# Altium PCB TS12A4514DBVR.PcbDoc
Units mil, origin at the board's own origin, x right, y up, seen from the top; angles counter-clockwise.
Board outline 588 x 300 mil, 2 copper layers (Top, Bottom), stack 61.811 mil thick; 3 components, 5 nets, 10 pads, 0 vias.
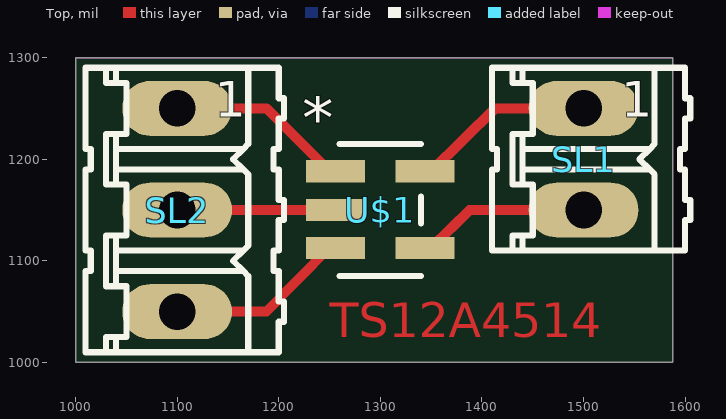
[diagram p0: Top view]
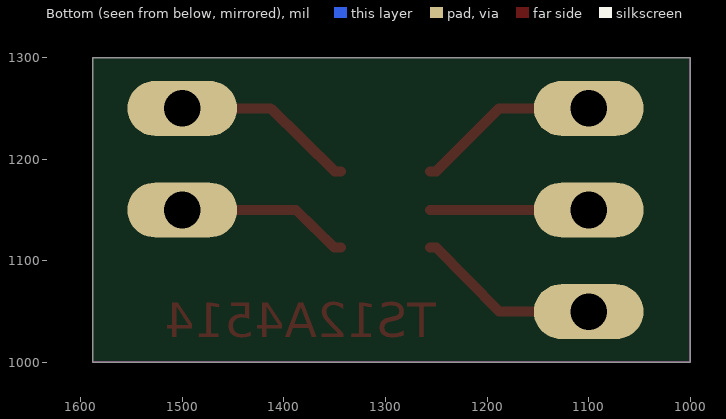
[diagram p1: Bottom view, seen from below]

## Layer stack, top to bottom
Top Solder: solder mask 0.4, Solder Resist, Dk 3.5
Top: signal copper 1.378
Dielectric 1: core 59.0551, FR-4, Dk 4.8
Bottom: signal copper 1.378
Bottom Solder: solder mask 0.4, Solder Resist, Dk 3.5

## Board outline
1000,1000 1588,1000 1588,1300 1000,1300

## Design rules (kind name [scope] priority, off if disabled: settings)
Clearance mdViaVia [IsVia vs IsVia] p1: gap=8
Clearance mdPadVia [IsPad vs IsVia] p2: gap=8
Clearance mdPadPad [IsPad vs IsPad] p3: gap=8
Clearance mdWireVia [(InLayerClass('Signal Layers') AND IsTrack) vs IsVia] p4: gap=8
Clearance mdWirePad [(InLayerClass('Signal Layers') AND IsTrack) vs IsPad] p5: gap=8
Clearance mdWireWire [(InLayerClass('Signal Layers') AND IsTrack) vs (InLayerClass('Signal Layers') AND IsTrack)] p6: gap=8
Clearance [All] p7: gap=8
HoleSize [All] p1: absolutevalues=TRUE maxlimit=100000 minlimit=24 maxpercent=80.000 minpercent=20.000
HoleToHoleClearance [All] p1: gap=8 allowstackedmicrovias=TRUE
PolygonConnect ThermalVias [IsVia] p1: connectstyle=Direct reliefconductorwidth=10 reliefentries=4 polygonreliefangle="90 Angle" airgapwidth=10
PolygonConnect [All] p2: connectstyle=Relief reliefconductorwidth=10 reliefentries=4 polygonreliefangle="90 Angle" airgapwidth=10
RoutingVias [All] p1: holewidth=28 width=50 viastyle="Through Hole" minholewidth=28 minwidth=50 maxholewidth=28 maxwidth=50
SilkToSilkClearance [All] p1 off: silktosilkclearance=10
SilkToSolderMaskClearance [IsPad] p1 off: minsilkscreentomaskgap=10 clearancetoexposedcopper=TRUE
SolderMaskExpansion [All] p1: expansion=4
UnpouredPolygon [All] p1: allowunpoured=FALSE
Width [All] p1: maxlimit=100000 minlimit=10 preferedwidth=10
25 further rules are at their usual default settings.

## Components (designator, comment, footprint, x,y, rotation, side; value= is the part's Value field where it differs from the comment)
SL1 "" 02P 1500,1200 r270 top
SL2 "" 03P 1100,1150 r270 top
U$1 "" DBV5 1300,1150 r0 top

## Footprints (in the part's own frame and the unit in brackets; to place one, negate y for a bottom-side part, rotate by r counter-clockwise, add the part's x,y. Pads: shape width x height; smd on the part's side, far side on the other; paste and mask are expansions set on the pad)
02P [mil] "02P"
  oval 54x108 hole 36: 1(-50,0) 2(50,0)
  silkscreen extent -90,-90 90,105
03P [mil] "03P"
  oval 54x108 hole 36: 1(-100,0) 2(0,0) 3(100,0)
  silkscreen extent -140,-90 140,105
DBV5 [mil] "DBV5"
  rect 58x22 smd: 1(-44,38) 2(-44,0) 3(-44,-37.4) 4(44,-37.4) 5(44,38)
  silkscreen extent -40,-65 40,65

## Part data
SL1: library part 02P
SL2: library part 03P
U$1: library part DBV5

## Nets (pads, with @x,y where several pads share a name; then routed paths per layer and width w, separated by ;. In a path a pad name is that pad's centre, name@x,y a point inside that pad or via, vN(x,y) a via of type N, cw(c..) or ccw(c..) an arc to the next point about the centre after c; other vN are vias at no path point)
N$1: SL1.1 U$1.5 | length 181.4
  Top w10: U$1.5 1350,1188 1413,1250 SL1.1
N$2: SL1.2 U$1.4 | length 171
  Top w10: U$1.4@1344,1113 1350,1113 1388,1150 SL1.2
N$3: SL2.1 U$1.1 | length 181.7
  Top w10: SL2.1 1188,1250 1250,1188 U$1.1
N$4: SL2.2 U$1.2 | length 156
  Top w10: SL2.2 U$1.2
N$5: SL2.3 U$1.3 | length 182.4
  Top w10: SL2.3 1188,1050 1250,1113 U$1.3@1256,1113

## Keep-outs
Keep-Out Layer:
  the board outline again, w0

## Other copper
Top:
  text "TS12A4514" at 1250,1025 h34

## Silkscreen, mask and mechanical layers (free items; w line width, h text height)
Dimension:
  the board outline again, w0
